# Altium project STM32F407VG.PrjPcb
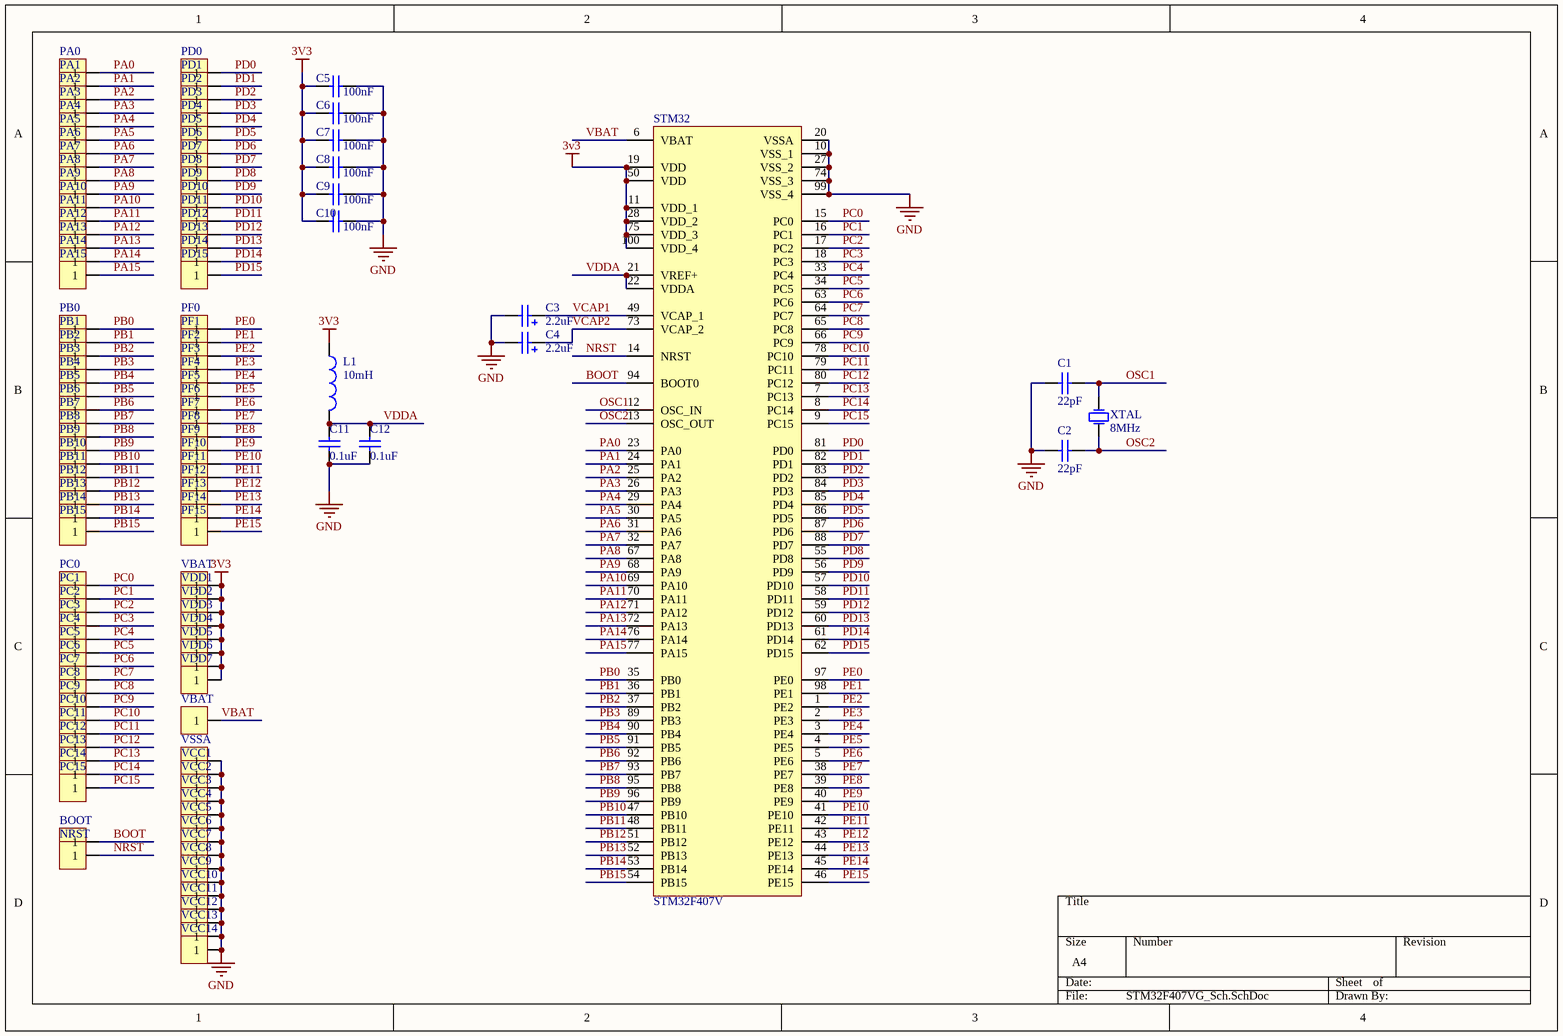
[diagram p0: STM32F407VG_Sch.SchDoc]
1 sheet, 121 parts. Net scope: global (net labels, ports and power ports of the same name join across sheets).
Board files: STM32F407VG_Pcb.PcbDoc, STM32F407VG2_Pcb.PcbDoc

## Sheet STM32F407VG_Sch.SchDoc
size A4

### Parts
(Parts that share a designator on the sheet are numbered #1, #2 ... from top to bottom, then left to right.)
BOOT  Header 1  [HDR1X1]  (value not drawn)
C1  value 22pF  [0603]  (hidden comment: Cap)
C2  value 22pF  [0603]  (hidden comment: Cap)
C3  2.2uf  [0805]
C4  2.2uf  [0805]
C5  value 100nF  [0603]  (hidden comment: Cap)
C6  value 100nF  [0603]  (hidden comment: Cap)
C7  value 100nF  [0603]  (hidden comment: Cap)
C8  value 100nF  [0603]  (hidden comment: Cap)
C9  value 100nF  [0603]  (hidden comment: Cap)
C10  value 100nF  [0603]  (hidden comment: Cap)
C11  value 0.1uF  [0603]  (hidden comment: Cap)
C12  value 0.1uF  [0603]  (hidden comment: Cap)
L1  value 10mH  [0603]  (hidden comment: Inductor)
NRST  Header 1  [HDR1X1]  (value not drawn)
PA0  Header 1  [HDR1X1]  (value not drawn)
PA1  Header 1  [HDR1X1]  (value not drawn)
PA2  Header 1  [HDR1X1]  (value not drawn)
PA3  Header 1  [HDR1X1]  (value not drawn)
PA4  Header 1  [HDR1X1]  (value not drawn)
PA5  Header 1  [HDR1X1]  (value not drawn)
PA6  Header 1  [HDR1X1]  (value not drawn)
PA7  Header 1  [HDR1X1]  (value not drawn)
PA8  Header 1  [HDR1X1]  (value not drawn)
PA9  Header 1  [HDR1X1]  (value not drawn)
PA10  Header 1  [HDR1X1]  (value not drawn)
PA11  Header 1  [HDR1X1]  (value not drawn)
PA12  Header 1  [HDR1X1]  (value not drawn)
PA13  Header 1  [HDR1X1]  (value not drawn)
PA14  Header 1  [HDR1X1]  (value not drawn)
PA15  Header 1  [HDR1X1]  (value not drawn)
PB0  Header 1  [HDR1X1]  (value not drawn)
PB1  Header 1  [HDR1X1]  (value not drawn)
PB2  Header 1  [HDR1X1]  (value not drawn)
PB3  Header 1  [HDR1X1]  (value not drawn)
PB4  Header 1  [HDR1X1]  (value not drawn)
PB5  Header 1  [HDR1X1]  (value not drawn)
PB6  Header 1  [HDR1X1]  (value not drawn)
PB7  Header 1  [HDR1X1]  (value not drawn)
PB8  Header 1  [HDR1X1]  (value not drawn)
PB9  Header 1  [HDR1X1]  (value not drawn)
PB10  Header 1  [HDR1X1]  (value not drawn)
PB11  Header 1  [HDR1X1]  (value not drawn)
PB12  Header 1  [HDR1X1]  (value not drawn)
PB13  Header 1  [HDR1X1]  (value not drawn)
PB14  Header 1  [HDR1X1]  (value not drawn)
PB15  Header 1  [HDR1X1]  (value not drawn)
PC0  Header 1  [HDR1X1]  (value not drawn)
PC1  Header 1  [HDR1X1]  (value not drawn)
PC2  Header 1  [HDR1X1]  (value not drawn)
PC3  Header 1  [HDR1X1]  (value not drawn)
PC4  Header 1  [HDR1X1]  (value not drawn)
PC5  Header 1  [HDR1X1]  (value not drawn)
PC6  Header 1  [HDR1X1]  (value not drawn)
PC7  Header 1  [HDR1X1]  (value not drawn)
PC8  Header 1  [HDR1X1]  (value not drawn)
PC9  Header 1  [HDR1X1]  (value not drawn)
PC10  Header 1  [HDR1X1]  (value not drawn)
PC11  Header 1  [HDR1X1]  (value not drawn)
PC12  Header 1  [HDR1X1]  (value not drawn)
PC13  Header 1  [HDR1X1]  (value not drawn)
PC14  Header 1  [HDR1X1]  (value not drawn)
PC15  Header 1  [HDR1X1]  (value not drawn)
PD0  Header 1  [HDR1X1]  (value not drawn)
PD1  Header 1  [HDR1X1]  (value not drawn)
PD2  Header 1  [HDR1X1]  (value not drawn)
PD3  Header 1  [HDR1X1]  (value not drawn)
PD4  Header 1  [HDR1X1]  (value not drawn)
PD5  Header 1  [HDR1X1]  (value not drawn)
PD6  Header 1  [HDR1X1]  (value not drawn)
PD7  Header 1  [HDR1X1]  (value not drawn)
PD8  Header 1  [HDR1X1]  (value not drawn)
PD9  Header 1  [HDR1X1]  (value not drawn)
PD10  Header 1  [HDR1X1]  (value not drawn)
PD11  Header 1  [HDR1X1]  (value not drawn)
PD12  Header 1  [HDR1X1]  (value not drawn)
PD13  Header 1  [HDR1X1]  (value not drawn)
PD14  Header 1  [HDR1X1]  (value not drawn)
PD15  Header 1  [HDR1X1]  (value not drawn)
PF0  Header 1  [HDR1X1]  (value not drawn)
PF1  Header 1  [HDR1X1]  (value not drawn)
PF2  Header 1  [HDR1X1]  (value not drawn)
PF3  Header 1  [HDR1X1]  (value not drawn)
PF4  Header 1  [HDR1X1]  (value not drawn)
PF5  Header 1  [HDR1X1]  (value not drawn)
PF6  Header 1  [HDR1X1]  (value not drawn)
PF7  Header 1  [HDR1X1]  (value not drawn)
PF8  Header 1  [HDR1X1]  (value not drawn)
PF9  Header 1  [HDR1X1]  (value not drawn)
PF10  Header 1  [HDR1X1]  (value not drawn)
PF11  Header 1  [HDR1X1]  (value not drawn)
PF12  Header 1  [HDR1X1]  (value not drawn)
PF13  Header 1  [HDR1X1]  (value not drawn)
PF14  Header 1  [HDR1X1]  (value not drawn)
PF15  Header 1  [HDR1X1]  (value not drawn)
STM32  STM32F407V  [STM32F_100]
VBAT#1  Header 1  [HDR1X1]  (value not drawn)
VBAT#2  Header 1  [HDR1X1]  (value not drawn)
VCC1  Header 1  [HDR1X1]  (value not drawn)
VCC2  Header 1  [HDR1X1]  (value not drawn)
VCC3  Header 1  [HDR1X1]  (value not drawn)
VCC4  Header 1  [HDR1X1]  (value not drawn)
VCC5  Header 1  [HDR1X1]  (value not drawn)
VCC6  Header 1  [HDR1X1]  (value not drawn)
VCC7  Header 1  [HDR1X1]  (value not drawn)
VCC8  Header 1  [HDR1X1]  (value not drawn)
VCC9  Header 1  [HDR1X1]  (value not drawn)
VCC10  Header 1  [HDR1X1]  (value not drawn)
VCC11  Header 1  [HDR1X1]  (value not drawn)
VCC12  Header 1  [HDR1X1]  (value not drawn)
VCC13  Header 1  [HDR1X1]  (value not drawn)
VCC14  Header 1  [HDR1X1]  (value not drawn)
VDD1  Header 1  [HDR1X1]  (value not drawn)
VDD2  Header 1  [HDR1X1]  (value not drawn)
VDD3  Header 1  [HDR1X1]  (value not drawn)
VDD4  Header 1  [HDR1X1]  (value not drawn)
VDD5  Header 1  [HDR1X1]  (value not drawn)
VDD6  Header 1  [HDR1X1]  (value not drawn)
VDD7  Header 1  [HDR1X1]  (value not drawn)
VSSA  Header 1  [HDR1X1]  (value not drawn)
XTAL  CLK: 8MHz  [XTAL_5032]  (hidden comment: XTAL)

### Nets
3V3: C5.1 C6.1 C7.1 C8.1 C9.1 C10.1 L1.1 STM32.11(VDD_1) STM32.19(VDD) STM32.28(VDD_2) STM32.50(VDD) STM32.75(VDD_3) STM32.100(VDD_4) VBAT#1.1 VDD1.1 VDD2.1 VDD3.1 VDD4.1 VDD5.1 VDD6.1 VDD7.1
GND: C1.1 C2.2 C3.2 C4.2 C5.2 C6.2 C7.2 C8.2 C9.2 C10.2 C11.1 C12.1 STM32.10(VSS_1) STM32.20(VSSA) STM32.27(VSS_2) STM32.74(VSS_3) STM32.99(VSS_4) VCC1.1 VCC2.1 VCC3.1 VCC4.1 VCC5.1 VCC6.1 VCC7.1 VCC8.1 VCC9.1 VCC10.1 VCC11.1 VCC12.1 VCC13.1 VCC14.1 VSSA.1
BOOT: BOOT.1 STM32.94(BOOT0)
NRST: NRST.1 STM32.14(NRST)
OSC1: C1.2 STM32.12(OSC_IN) XTAL.1(OSC1)
OSC2: C2.1 STM32.13(OSC_OUT) XTAL.2(OSC2)
PA0: PA0.1 STM32.23(PA0)
PA1: PA1.1 STM32.24(PA1)
PA2: PA2.1 STM32.25(PA2)
PA3: PA3.1 STM32.26(PA3)
PA4: PA4.1 STM32.29(PA4)
PA5: PA5.1 STM32.30(PA5)
PA6: PA6.1 STM32.31(PA6)
PA7: PA7.1 STM32.32(PA7)
PA8: PA8.1 STM32.67(PA8)
PA9: PA9.1 STM32.68(PA9)
PA10: PA10.1 STM32.69(PA10)
PA11: PA11.1 STM32.70(PA11)
PA12: PA12.1 STM32.71(PA12)
PA13: PA13.1 STM32.72(PA13)
PA14: PA14.1 STM32.76(PA14)
PA15: PA15.1 STM32.77(PA15)
PB0: PB0.1 STM32.35(PB0)
PB1: PB1.1 STM32.36(PB1)
PB2: PB2.1 STM32.37(PB2)
PB3: PB3.1 STM32.89(PB3)
PB4: PB4.1 STM32.90(PB4)
PB5: PB5.1 STM32.91(PB5)
PB6: PB6.1 STM32.92(PB6)
PB7: PB7.1 STM32.93(PB7)
PB8: PB8.1 STM32.95(PB8)
PB9: PB9.1 STM32.96(PB9)
PB10: PB10.1 STM32.47(PB10)
PB11: PB11.1 STM32.48(PB11)
PB12: PB12.1 STM32.51(PB12)
PB13: PB13.1 STM32.52(PB13)
PB14: PB14.1 STM32.53(PB14)
PB15: PB15.1 STM32.54(PB15)
PC0: PC0.1 STM32.15(PC0)
PC1: PC1.1 STM32.16(PC1)
PC2: PC2.1 STM32.17(PC2)
PC3: PC3.1 STM32.18(PC3)
PC4: PC4.1 STM32.33(PC4)
PC5: PC5.1 STM32.34(PC5)
PC6: PC6.1 STM32.63(PC6)
PC7: PC7.1 STM32.64(PC7)
PC8: PC8.1 STM32.65(PC8)
PC9: PC9.1 STM32.66(PC9)
PC10: PC10.1 STM32.78(PC10)
PC11: PC11.1 STM32.79(PC11)
PC12: PC12.1 STM32.80(PC12)
PC13: PC13.1 STM32.7(PC13)
PC14: PC14.1 STM32.8(PC14)
PC15: PC15.1 STM32.9(PC15)
PD0: PD0.1 STM32.81(PD0)
PD1: PD1.1 STM32.82(PD1)
PD2: PD2.1 STM32.83(PD2)
PD3: PD3.1 STM32.84(PD3)
PD4: PD4.1 STM32.85(PD4)
PD5: PD5.1 STM32.86(PD5)
PD6: PD6.1 STM32.87(PD6)
PD7: PD7.1 STM32.88(PD7)
PD8: PD8.1 STM32.55(PD8)
PD9: PD9.1 STM32.56(PD9)
PD10: PD10.1 STM32.57(PD10)
PD11: PD11.1 STM32.58(PD11)
PD12: PD12.1 STM32.59(PD12)
PD13: PD13.1 STM32.60(PD13)
PD14: PD14.1 STM32.61(PD14)
PD15: PD15.1 STM32.62(PD15)
PE0: PF0.1 STM32.97(PE0)
PE1: PF1.1 STM32.98(PE1)
PE2: PF2.1 STM32.1(PE2)
PE3: PF3.1 STM32.2(PE3)
PE4: PF4.1 STM32.3(PE4)
PE5: PF5.1 STM32.4(PE5)
PE6: PF6.1 STM32.5(PE6)
PE7: PF7.1 STM32.38(PE7)
PE8: PF8.1 STM32.39(PE8)
PE9: PF9.1 STM32.40(PE9)
PE10: PF10.1 STM32.41(PE10)
PE11: PF11.1 STM32.42(PE11)
PE12: PF12.1 STM32.43(PE12)
PE13: PF13.1 STM32.44(PE13)
PE14: PF14.1 STM32.45(PE14)
PE15: PF15.1 STM32.46(PE15)
VBAT: STM32.6(VBAT) VBAT#2.1
VCAP1: C3.1 STM32.49(VCAP_1)
VCAP2: C4.1 STM32.73(VCAP_2)
VDDA: C11.2 C12.2 L1.2 STM32.21(VREF+) STM32.22(VDDA)

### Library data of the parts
BOOT NRST PA0-PA15 PB0-PB15 PC0-PC15 PD0-PD15 PF0-PF15 VBAT#1 VBAT#2 VCC1-VCC14 VDD1-VDD7 VSSA = Header 1: Header, 1-Pin
C1 C2 C5-C12 = Cap: Capacitor
C3 C4 = Cap Pol2: Polarized Capacitor (Axial)
L1 = Inductor: Code_IEC: 1005
STM32 = STM32F407V: MCU
XTAL = XTAL: Crystal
